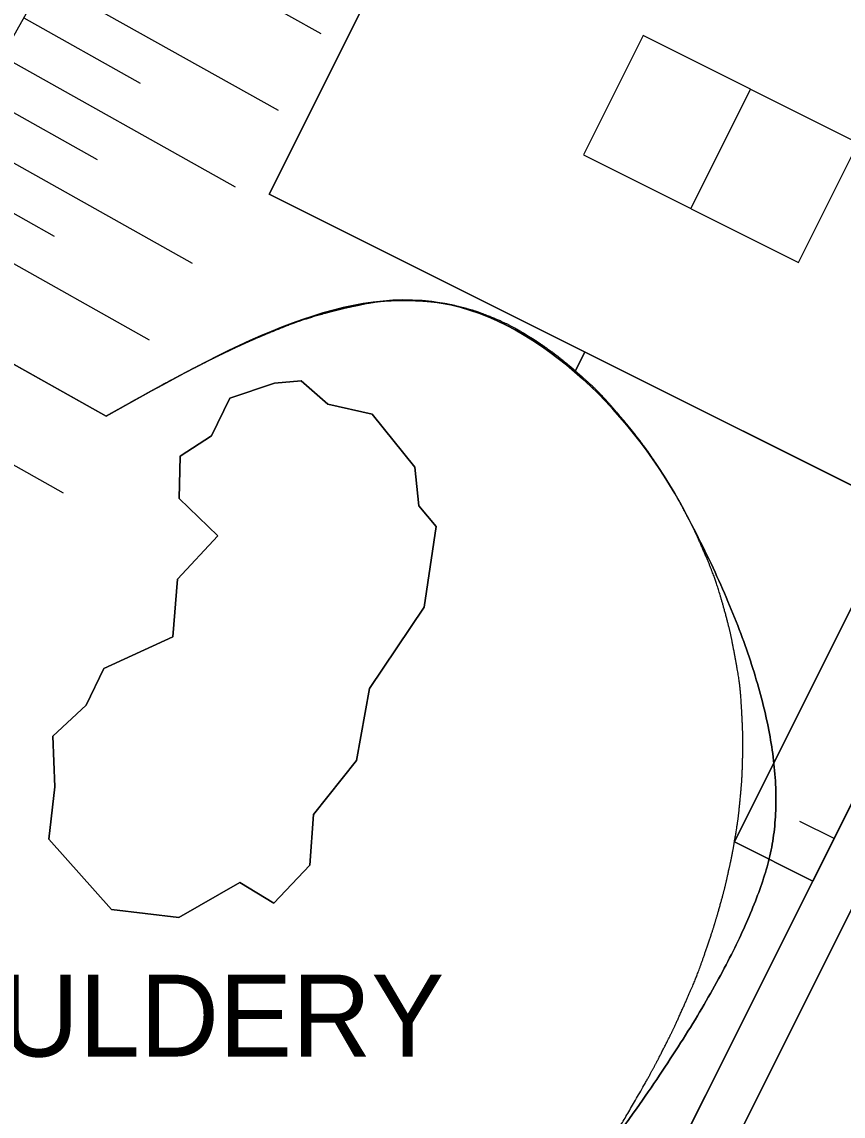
# Model space of a CAD drawing. Extents: x -504998 to -504814, y -1117353 to -1117234.
# Drawn here: x -504964.2 to -504954.85, y -1117274.95 to -1117262.48 of the extents above; entities that cross this region are included whole.
import ezdxf

# ---------------------------------------------------------------- set-up
doc = ezdxf.new("R2010")
doc.units = 0
for name, color, linetype in [('01_ST tenká', 7, 'Continuous'), ('03_POPIS', 7, 'Continuous'), ('05_ZARIZ_PREDMETY', 7, 'Continuous'), ('_01_pl', 7, 'Continuous'), ('_01_sport_plochy', 7, 'Continuous'), ('_01_ST tenká', 7, 'Continuous'), ('_01_svah', 7, 'Continuous'), ('_02_pl_ cesta', 7, 'Continuous')]:
    doc.layers.add(name, color=color, linetype=linetype)

msp = doc.modelspace()

# ---------------------------------------------------------------- linework, layer by layer
at = {"layer": '01_ST tenká'}
for p, q in [((-504956.089, -1117271.824), (-504955.197, -1117272.27)), ((-504955.197, -1117272.27), (-504961.34, -1117284.555))]:
    msp.add_line(p, q, dxfattribs=at)
for points in [[(-504957.344, -1117256.356), (-504961.388, -1117264.442), (-504954.197, -1117268.038), (-504950.153, -1117259.952)], [(-504962.432, -1117268.828), (-504961.974, -1117268.335), (-504962.413, -1117267.909), (-504962.401, -1117267.43), (-504962.045, -1117267.197), (-504961.835, -1117266.766), (-504961.328, -1117266.595), (-504961.023, -1117266.571), (-504960.721, -1117266.835), (-504960.214, -1117266.948), (-504959.728, -1117267.552), (-504959.683, -1117267.995), (-504959.487, -1117268.228), (-504959.621, -1117269.148), (-504960.245, -1117270.075), (-504960.395, -1117270.897), (-504960.883, -1117271.513), (-504960.924, -1117272.088), (-504961.336, -1117272.52), (-504961.722, -1117272.287), (-504962.417, -1117272.683), (-504963.183, -1117272.595), (-504963.898, -1117271.791), (-504963.829, -1117271.196), (-504963.851, -1117270.617), (-504963.472, -1117270.267), (-504963.27, -1117269.846), (-504962.487, -1117269.487)]]:
    msp.add_lwpolyline(points, close=True, dxfattribs=at)
msp.add_lwpolyline([(-504963.246, -1117266.973), (-504965.897, -1117265.484), (-504971.638, -1117275.705)], dxfattribs=at)
for points, degree in [([(-504985.829, -1117325.121), (-504985.05, -1117323.979), (-504984.293, -1117322.775), (-504983.459, -1117321.036), (-504983.268, -1117320.596), (-504982.922, -1117319.691), (-504982.768, -1117319.221), (-504982.381, -1117317.806), (-504982.223, -1117316.873), (-504981.98, -1117315.069), (-504981.89, -1117314.207), (-504981.717, -1117312.468), (-504981.488, -1117309.863), (-504981.354, -1117307.26), (-504981.285, -1117304.645), (-504981.273, -1117303.772), (-504981.27, -1117302.02), (-504981.281, -1117301.138), (-504981.332, -1117298.524), (-504981.381, -1117296.816), (-504981.301, -1117293.521), (-504981.172, -1117291.938), (-504980.719, -1117289.69), (-504980.52, -1117288.956), (-504980.034, -1117287.473), (-504979.748, -1117286.73), (-504978.792, -1117284.494), (-504978.024, -1117282.996), (-504976.816, -1117280.721), (-504976.408, -1117279.961), (-504975.591, -1117278.451), (-504973.537, -1117274.688), (-504971.441, -1117270.981), (-504966.382, -1117262.111), (-504962.97, -1117256.232), (-504959.251, -1117249.407), (-504958.839, -1117248.646), (-504958.02, -1117247.117), (-504957.612, -1117246.345), (-504956.403, -1117244.058), (-504955.608, -1117242.573), (-504954.317, -1117240.515), (-504953.87, -1117239.857), (-504952.93, -1117238.612), (-504952.439, -1117238.031), (-504951.757, -1117237.321), (-504951.607, -1117237.17), (-504951.453, -1117237.019)], 3), ([(-504985.829, -1117321.311), (-504985.345, -1117320.405), (-504984.404, -1117318.259), (-504983.525, -1117311.535), (-504983.019, -1117301.967), (-504983.843, -1117289.896), (-504974.219, -1117271.163), (-504963.977, -1117254.546), (-504956.335, -1117239.546), (-504954.188, -1117237.019)], 3), ([(-504956.657, -1117268.053), (-504957.218, -1117266.996), (-504959.322, -1117264.774), (-504961.848, -1117266.19), (-504963.246, -1117266.973)], 3), ([(-504958.182, -1117276.163), (-504956.174, -1117273.634), (-504955.279, -1117270.647), (-504956.657, -1117268.053)], 2), ([(-504956.15, -1117272.132), (-504956.127, -1117272.03), (-504956.107, -1117271.927), (-504956.089, -1117271.824)], 2), ([(-504956.253, -1117272.548), (-504956.214, -1117272.41), (-504956.18, -1117272.271), (-504956.15, -1117272.132)], 2), ([(-504956.381, -1117272.963), (-504956.334, -1117272.825), (-504956.292, -1117272.687), (-504956.253, -1117272.548)], 2), ([(-504956.707, -1117273.786), (-504956.583, -1117273.513), (-504956.474, -1117273.239), (-504956.381, -1117272.963)], 2), ([(-504956.903, -1117274.194), (-504956.834, -1117274.058), (-504956.768, -1117273.923), (-504956.707, -1117273.786)], 2), ([(-504957.12, -1117274.598), (-504957.044, -1117274.464), (-504956.972, -1117274.329), (-504956.903, -1117274.194)], 2), ([(-504958.182, -1117276.163), (-504957.781, -1117275.657), (-504957.423, -1117275.133), (-504957.12, -1117274.598)], 2)]:
    msp.add_open_spline(points, degree=degree, dxfattribs=at)
at = {"layer": '05_ZARIZ_PREDMETY'}
msp.add_lwpolyline([(-504962.045, -1117267.197), (-504961.835, -1117266.766), (-504961.328, -1117266.595), (-504961.023, -1117266.571), (-504960.721, -1117266.835), (-504960.214, -1117266.948), (-504959.728, -1117267.552), (-504959.683, -1117267.995), (-504959.487, -1117268.228), (-504959.621, -1117269.148), (-504960.245, -1117270.075), (-504960.395, -1117270.897), (-504960.883, -1117271.513), (-504960.924, -1117272.088), (-504961.336, -1117272.52), (-504961.722, -1117272.287), (-504962.417, -1117272.683), (-504963.183, -1117272.595), (-504963.898, -1117271.791), (-504963.829, -1117271.196), (-504963.851, -1117270.617), (-504963.472, -1117270.267), (-504963.27, -1117269.846), (-504962.487, -1117269.487), (-504962.432, -1117268.828), (-504961.974, -1117268.335), (-504962.413, -1117267.909), (-504962.401, -1117267.43)], close=True, dxfattribs=at)
at = {"layer": '_01_pl'}
for p, q in [((-504957.792, -1117266.24), (-504957.901, -1117266.457)), ((-504954.954, -1117271.786), (-504955.343, -1117271.591))]:
    msp.add_line(p, q, dxfattribs=at)
for points in [[(-504963.246, -1117266.973), (-504965.897, -1117265.484), (-504960.021, -1117255.022), (-504957.41, -1117256.488), (-504961.388, -1117264.442), (-504957.792, -1117266.24), (-504957.901, -1117266.457)], [(-504956.089, -1117271.822), (-504954.197, -1117268.037), (-504954.197, -1117268.038), (-504950.153, -1117259.952), (-504949.386, -1117258.414), (-504884.534, -1117290.845)], [(-504956.089, -1117271.824), (-504955.197, -1117272.27), (-504948.984, -1117259.846), (-504961.34, -1117284.555)], [(-504913.109, -1117277.786), (-504939.85, -1117264.413), (-504943.617, -1117262.53), (-504948.984, -1117259.846), (-504955.197, -1117272.27), (-504956.089, -1117271.824)], [(-504971.638, -1117275.705), (-504965.897, -1117265.484), (-504963.246, -1117266.973)], [(-504957.901, -1117266.457), (-504957.792, -1117266.24), (-504954.197, -1117268.037), (-504956.089, -1117271.822)]]:
    msp.add_lwpolyline(points, dxfattribs=at)
for points in [[(-504955.359, -1117265.22), (-504954.679, -1117263.861), (-504957.13, -1117262.635), (-504957.81, -1117263.995)], [(-504962.045, -1117267.197), (-504961.835, -1117266.766), (-504961.328, -1117266.595), (-504961.023, -1117266.571), (-504960.721, -1117266.835), (-504960.214, -1117266.948), (-504959.728, -1117267.552), (-504959.683, -1117267.995), (-504959.487, -1117268.228), (-504959.621, -1117269.148), (-504960.245, -1117270.075), (-504960.395, -1117270.897), (-504960.883, -1117271.513), (-504960.924, -1117272.088), (-504961.336, -1117272.52), (-504961.722, -1117272.287), (-504962.417, -1117272.683), (-504963.183, -1117272.595), (-504963.898, -1117271.791), (-504963.829, -1117271.196), (-504963.851, -1117270.617), (-504963.472, -1117270.267), (-504963.27, -1117269.846), (-504962.487, -1117269.487), (-504962.432, -1117268.828), (-504961.974, -1117268.335), (-504962.413, -1117267.909), (-504962.401, -1117267.43)], [(-504962.487, -1117269.487), (-504963.27, -1117269.846), (-504963.472, -1117270.267), (-504963.851, -1117270.617), (-504963.829, -1117271.196), (-504963.898, -1117271.791), (-504963.183, -1117272.595), (-504962.417, -1117272.683), (-504961.722, -1117272.287), (-504961.336, -1117272.52), (-504960.924, -1117272.088), (-504960.883, -1117271.513), (-504960.395, -1117270.897), (-504960.245, -1117270.075), (-504959.621, -1117269.148), (-504959.487, -1117268.228), (-504959.683, -1117267.995), (-504959.728, -1117267.552), (-504960.214, -1117266.948), (-504960.721, -1117266.835), (-504961.023, -1117266.571), (-504961.328, -1117266.595), (-504961.835, -1117266.766), (-504962.045, -1117267.197), (-504962.401, -1117267.43), (-504962.413, -1117267.909), (-504961.974, -1117268.335), (-504962.432, -1117268.828)]]:
    msp.add_lwpolyline(points, close=True, dxfattribs=at)
for points, degree in [([(-504963.246, -1117266.973), (-504961.848, -1117266.19), (-504959.322, -1117264.774), (-504957.218, -1117266.996), (-504956.657, -1117268.053)], 3), ([(-504960.555, -1117265.751), (-504960.622, -1117265.767), (-504960.689, -1117265.784), (-504960.757, -1117265.803)], 2), ([(-504959.76, -1117265.659), (-504960.021, -1117265.655), (-504960.286, -1117265.689), (-504960.555, -1117265.751)], 2), ([(-504959.565, -1117265.67), (-504959.63, -1117265.664), (-504959.695, -1117265.661), (-504959.76, -1117265.659)], 2), ([(-504959.18, -1117265.737), (-504959.307, -1117265.704), (-504959.436, -1117265.682), (-504959.565, -1117265.67)], 2), ([(-504958.876, -1117265.838), (-504958.977, -1117265.798), (-504959.078, -1117265.764), (-504959.18, -1117265.737)], 2), ([(-504960.757, -1117265.803), (-504960.96, -1117265.861), (-504961.164, -1117265.933), (-504961.37, -1117266.017)], 2), ([(-504958.433, -1117266.063), (-504958.578, -1117265.975), (-504958.726, -1117265.899), (-504958.876, -1117265.838)], 2), ([(-504961.576, -1117266.104), (-504961.645, -1117266.134), (-504961.714, -1117266.166), (-504961.783, -1117266.198)], 2), ([(-504961.37, -1117266.017), (-504961.439, -1117266.045), (-504961.507, -1117266.074), (-504961.576, -1117266.104)], 2), ([(-504958.29, -1117266.155), (-504958.338, -1117266.123), (-504958.385, -1117266.092), (-504958.433, -1117266.063)], 2), ([(-504961.783, -1117266.198), (-504961.852, -1117266.231), (-504961.922, -1117266.264), (-504961.991, -1117266.298)], 2), ([(-504958.012, -1117266.363), (-504958.103, -1117266.289), (-504958.196, -1117266.22), (-504958.29, -1117266.155)], 2), ([(-504961.991, -1117266.298), (-504962.06, -1117266.332), (-504962.13, -1117266.367), (-504962.199, -1117266.403)], 2), ([(-504957.901, -1117266.457), (-504957.938, -1117266.425), (-504957.975, -1117266.394), (-504958.012, -1117266.363)], 2), ([(-504962.199, -1117266.403), (-504962.338, -1117266.474), (-504962.478, -1117266.549), (-504962.617, -1117266.624)], 2), ([(-504957.373, -1117266.995), (-504957.538, -1117266.801), (-504957.715, -1117266.619), (-504957.901, -1117266.457)], 2), ([(-504962.617, -1117266.624), (-504962.687, -1117266.662), (-504962.757, -1117266.701), (-504962.827, -1117266.739)], 2), ([(-504962.827, -1117266.739), (-504962.896, -1117266.778), (-504962.966, -1117266.817), (-504963.036, -1117266.856)], 2), ([(-504963.036, -1117266.856), (-504963.106, -1117266.895), (-504963.176, -1117266.934), (-504963.246, -1117266.973)], 2), ([(-504957.256, -1117267.137), (-504957.294, -1117267.089), (-504957.333, -1117267.042), (-504957.373, -1117266.995)], 2), ([(-504956.934, -1117267.584), (-504957.034, -1117267.431), (-504957.142, -1117267.281), (-504957.256, -1117267.137)], 2), ([(-504956.657, -1117268.053), (-504956.741, -1117267.895), (-504956.834, -1117267.738), (-504956.934, -1117267.584)], 2), ([(-504956.657, -1117268.053), (-504955.279, -1117270.647), (-504956.174, -1117273.634), (-504958.182, -1117276.163)], 2), ([(-504956.467, -1117268.445), (-504956.525, -1117268.314), (-504956.588, -1117268.183), (-504956.657, -1117268.053)], 2), ([(-504956.186, -1117269.244), (-504956.259, -1117268.975), (-504956.352, -1117268.708), (-504956.467, -1117268.445)], 2), ([(-504956.094, -1117269.65), (-504956.119, -1117269.514), (-504956.15, -1117269.379), (-504956.186, -1117269.244)], 2), ([(-504955.999, -1117270.471), (-504956.011, -1117270.195), (-504956.042, -1117269.921), (-504956.094, -1117269.65)], 2), ([(-504955.996, -1117270.885), (-504955.992, -1117270.746), (-504955.993, -1117270.608), (-504955.999, -1117270.471)], 2), ([(-504956.02, -1117271.3), (-504956.007, -1117271.161), (-504955.999, -1117271.023), (-504955.996, -1117270.885)], 2), ([(-504956.089, -1117271.822), (-504956.059, -1117271.648), (-504956.036, -1117271.474), (-504956.02, -1117271.3)], 2), ([(-504956.15, -1117272.132), (-504956.127, -1117272.03), (-504956.107, -1117271.927), (-504956.089, -1117271.824)], 2), ([(-504956.089, -1117271.824), (-504956.089, -1117271.823), (-504956.089, -1117271.823), (-504956.089, -1117271.822)], 2), ([(-504956.253, -1117272.548), (-504956.214, -1117272.41), (-504956.18, -1117272.271), (-504956.15, -1117272.132)], 2), ([(-504956.381, -1117272.963), (-504956.334, -1117272.825), (-504956.292, -1117272.687), (-504956.253, -1117272.548)], 2), ([(-504956.707, -1117273.786), (-504956.583, -1117273.513), (-504956.474, -1117273.239), (-504956.381, -1117272.963)], 2), ([(-504956.903, -1117274.194), (-504956.834, -1117274.058), (-504956.768, -1117273.923), (-504956.707, -1117273.786)], 2), ([(-504957.12, -1117274.598), (-504957.044, -1117274.464), (-504956.972, -1117274.329), (-504956.903, -1117274.194)], 2), ([(-504958.182, -1117276.163), (-504957.781, -1117275.657), (-504957.423, -1117275.133), (-504957.12, -1117274.598)], 2)]:
    msp.add_open_spline(points, degree=degree, dxfattribs=at)
at = {"layer": '_01_sport_plochy'}
for points in [[(-504957.344, -1117256.356), (-504950.155, -1117259.952), (-504954.197, -1117268.038), (-504961.388, -1117264.442)], [(-504957.13, -1117262.635), (-504957.81, -1117263.995), (-504955.359, -1117265.22), (-504954.679, -1117263.861)]]:
    msp.add_lwpolyline(points, close=True, dxfattribs=at)
for points in [[(-504961.43, -1117284.592), (-504961.373, -1117284.62), (-504948.984, -1117259.846), (-504948.504, -1117260.086), (-504959.966, -1117283.007)], [(-504959.966, -1117283.007), (-504948.504, -1117260.086), (-504943.617, -1117262.53), (-504956.006, -1117287.304), (-504961.43, -1117284.592)]]:
    msp.add_lwpolyline(points, dxfattribs=at)
at = {"layer": '_01_ST tenká'}
for points in [[(-504948.984, -1117259.846), (-504961.373, -1117284.62), (-504956.006, -1117287.304), (-504943.617, -1117262.53)], [(-504957.13, -1117262.635), (-504957.81, -1117263.995), (-504955.359, -1117265.22), (-504954.679, -1117263.861)], [(-504955.905, -1117263.248), (-504956.585, -1117264.607), (-504956.585, -1117264.607), (-504955.905, -1117263.248)]]:
    msp.add_lwpolyline(points, close=True, dxfattribs=at)
at = {"layer": '_01_svah'}
for p, q in [((-504963.449, -1117261.125), (-504960.798, -1117262.614)), ((-504963.939, -1117261.997), (-504961.287, -1117263.486)), ((-504964.183, -1117262.433), (-504962.858, -1117263.177)), ((-504964.428, -1117262.869), (-504961.777, -1117264.358)), ((-504964.673, -1117263.305), (-504963.347, -1117264.049)), ((-504964.918, -1117263.741), (-504962.267, -1117265.23)), ((-504965.163, -1117264.177), (-504963.837, -1117264.921)), ((-504965.408, -1117264.612), (-504962.756, -1117266.102)), ((-504965.897, -1117265.484), (-504963.246, -1117266.973)), ((-504966.387, -1117266.356), (-504963.736, -1117267.845))]:
    msp.add_line(p, q, dxfattribs=at)
at = {"layer": '_02_pl_ cesta'}
for points in [[(-504983.664, -1117321.464), (-504983.459, -1117321.036), (-504983.268, -1117320.596), (-504982.922, -1117319.691), (-504982.768, -1117319.221), (-504982.381, -1117317.806), (-504982.223, -1117316.873), (-504981.98, -1117315.069), (-504981.89, -1117314.207), (-504981.717, -1117312.468), (-504981.488, -1117309.863), (-504981.354, -1117307.26), (-504981.285, -1117304.645), (-504981.273, -1117303.772), (-504981.27, -1117302.02), (-504981.281, -1117301.138), (-504981.332, -1117298.524), (-504981.381, -1117296.816), (-504981.301, -1117293.521), (-504981.172, -1117291.938), (-504980.719, -1117289.69), (-504980.52, -1117288.956), (-504980.034, -1117287.473), (-504979.748, -1117286.73), (-504978.792, -1117284.494), (-504978.024, -1117282.996), (-504976.816, -1117280.721), (-504976.408, -1117279.961), (-504975.591, -1117278.451), (-504973.537, -1117274.688), (-504971.441, -1117270.981), (-504966.382, -1117262.111), (-504962.97, -1117256.232), (-504959.251, -1117249.407), (-504958.839, -1117248.646), (-504958.02, -1117247.117), (-504957.612, -1117246.345), (-504956.403, -1117244.058), (-504955.608, -1117242.573), (-504954.317, -1117240.515), (-504953.87, -1117239.857), (-504952.93, -1117238.612), (-504952.439, -1117238.031), (-504951.904, -1117237.474)], [(-504959.462, -1117245.565), (-504965.694, -1117257.332), (-504973.391, -1117269.82), (-504980.458, -1117283.333), (-504981.18, -1117284.993)]]:
    msp.add_open_spline(points, degree=3, dxfattribs=at)

# ---------------------------------------------------------------- texts
at = {"layer": '03_POPIS'}
msp.add_text('BOULDERY', height=0.9331, dxfattribs=at).set_placement((-504966.258, -1117274.269))

doc.saveas('drawing.dxf')
